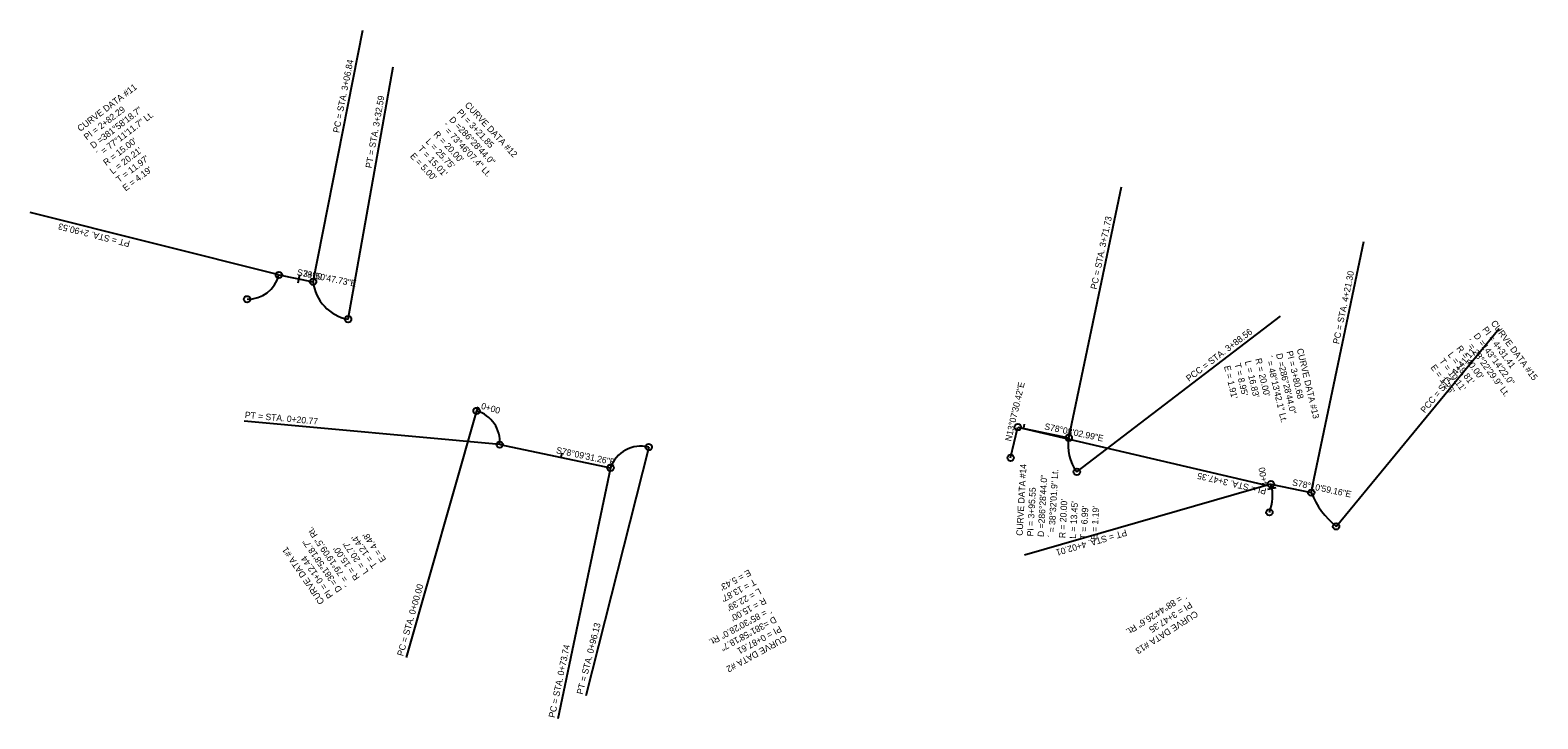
# Model space of a CAD drawing. Extents: x 1158784 to 1165006, y 610007 to 611539.
# Drawn here: x 1164301 to 1165006, y 610067 to 610389 of the extents above; entities that cross this region are included whole.
import ezdxf

# ---------------------------------------------------------------- set-up
doc = ezdxf.new("R2010")
doc.units = 0
for name, color, linetype in [('D_Roadway_Centerline', 7, 'Continuous'), ('D_Roadway_Centerline_Bearings', 7, 'Continuous'), ('D_Roadway_Centerline_CurveData', 7, 'Continuous'), ('D_Roadway_Centerline_Flags', 7, 'Continuous'), ('D_Roadway_Centerline_Text', 7, 'Continuous')]:
    doc.layers.add(name, color=color, linetype=linetype)

msp = doc.modelspace()

# ---------------------------------------------------------------- linework, layer by layer
at = {"layer": 'D_Roadway_Centerline'}
for p, q in [((1164417.28, 610274.76), (1164433.28, 610271.61)), ((1164759.67, 610189.2), (1164763.02, 610203.58)), ((1164763.02, 610203.58), (1164786.87, 610198.57)), ((1164520.59, 610195.37), (1164572.44, 610184.5)), ((1164881.46, 610176.87), (1164900.33, 610172.92))]:
    msp.add_line(p, q, dxfattribs=at)
for centre, radius, start, end in [((1164402.73, 610278.42), 15, 268.70224, 345.88884), ((1164453.17, 610273.75), 20, 186.14707, 259.9158), ((1164505.66, 610196.75), 15, 354.7361, 74.05542), ((1164586.65, 610179.69), 15, 75.80215, 161.30991), ((1164806.52, 610194.82), 20, 169.18321, 217.41157), ((1164862.24, 610171.32), 20, 337.56551, 16.09937), ((1164937.38, 610188), 40, 202.15271, 230.5277)]:
    msp.add_arc(centre, radius, start, end, dxfattribs=at)
at = {"layer": 'D_Roadway_Centerline_Flags'}
for points in [[(1164433.28, 610271.61), (1164456.5, 610389.34)], [(1164449.67, 610254.06), (1164470.68, 610372.2)], [(1164786.87, 610198.57), (1164811.55, 610316)], [(1164417.28, 610274.76), (1164300.9, 610304.02)], [(1164900.33, 610172.92), (1164924.91, 610290.38)], [(1164790.63, 610182.66), (1164885.95, 610255.57)], [(1164911.95, 610157.12), (1164988.24, 610249.76)], [(1164509.78, 610211.17), (1164476.81, 610095.79)], [(1164520.59, 610195.37), (1164401.1, 610206.38)], [(1164763.02, 610203.58), (1164879.88, 610176.33)], [(1164590.33, 610194.24), (1164560.89, 610077.9)], [(1164572.44, 610184.5), (1164547.81, 610067.05)], [(1164881.46, 610176.87), (1164766.16, 610143.59)]]:
    msp.add_lwpolyline(points, dxfattribs=at)
for centre in [(1164417.28, 610274.76), (1164433.28, 610271.61), (1164402.39, 610263.42), (1164449.67, 610254.06), (1164509.78, 610211.17), (1164763.02, 610203.58), (1164520.59, 610195.37), (1164590.33, 610194.24), (1164786.87, 610198.57), (1164759.67, 610189.2), (1164572.44, 610184.5), (1164790.63, 610182.66), (1164881.46, 610176.87), (1164900.33, 610172.92), (1164880.73, 610163.69), (1164911.95, 610157.12)]:
    msp.add_circle(centre, 1.5, dxfattribs=at)
at = {"layer": 'D_Roadway_Centerline_Text'}
for points in [[(1164426.96, 610274.89), (1164426.18, 610270.97)], [(1164510.33, 610213.09), (1164509.23, 610209.25)], [(1164766.02, 610204.99), (1164765.61, 610203.04)], [(1164549.61, 610191.33), (1164549.2, 610189.37)], [(1164879.95, 610174.55), (1164883.88, 610175.27)]]:
    msp.add_lwpolyline(points, dxfattribs=at)

# ---------------------------------------------------------------- texts
at = {"layer": 'D_Roadway_Centerline_Bearings'}
for s, rotation, p in [('S78%%d50\'47.73"E', 348.84659, (1164425.57, 610274.66)), ('N13%%d07\'30.42"E', 76.87488, (1164759.88, 610196.73)), ('S78%%d08\'02.99"E', 348.13416, (1164775.25, 610202.54)), ('S78%%d09\'31.26"E', 348.15868, (1164546.82, 610191.4)), ('S78%%d10\'59.16"E', 348.1831, (1164891.2, 610176.36))]:
    msp.add_text(s, height=3, rotation=rotation, dxfattribs=at).set_placement(p)
at = {"layer": 'D_Roadway_Centerline_CurveData'}
for s, rotation, p in [('CURVE DATA #11', 37.29554, (1164324.37, 610341.69)), ('PI = 2+82.29', 37.29554, (1164327.4, 610337.71)), ('D =381%%d58\'18.7"', 37.29554, (1164330.43, 610333.73)), ('´ = 77%%d11\'11.7" Lt.', 37.29554, (1164333.46, 610329.75)), ('D =286%%d28\'44.0"', 313.03144, (1164496.73, 610347.25)), ('PI = 3+21.85', 313.03144, (1164500.38, 610350.66)), ('CURVE DATA #12', 313.03144, (1164504.04, 610354.07)), ("R = 20.00'", 313.03144, (1164489.42, 610340.42)), ('´ = 73%%d46\'07.4" Lt.', 313.03144, (1164493.07, 610343.83)), ("R = 15.00'", 37.29554, (1164336.49, 610325.78)), ("T = 15.01'", 313.03144, (1164482.11, 610333.6)), ("L = 25.75'", 313.03144, (1164485.76, 610337.01)), ("L = 20.21'", 37.29554, (1164339.52, 610321.8)), ("T = 11.97'", 37.29554, (1164342.55, 610317.82)), ("E = 5.00'", 313.03144, (1164478.45, 610330.19)), ("E = 4.19'", 37.29554, (1164345.58, 610313.84)), ('PI = 4+31.41', 306.34021, (1164980.14, 610249.25)), ('CURVE DATA #15', 306.34021, (1164984.17, 610252.22)), ('´ = 28%%d22\'29.9" Lt.', 306.34021, (1164972.09, 610243.33)), ('D =143%%d14\'22.0"', 306.34021, (1164976.11, 610246.29)), ('´ = 48%%d13\'42.1" Lt.', 283.29739, (1164878.94, 610236.59)), ('D =286%%d28\'44.0"', 283.29739, (1164883.8, 610237.74)), ('PI = 3+80.68', 283.29739, (1164888.67, 610238.89)), ('CURVE DATA #13', 283.29739, (1164893.53, 610240.04)), ("T = 10.11'", 306.34021, (1164960, 610234.44)), ("L = 19.81'", 306.34021, (1164964.03, 610237.4)), ("R = 40.00'", 306.34021, (1164968.06, 610240.37)), ("E = 1.91'", 283.29739, (1164859.47, 610231.99)), ("T = 8.95'", 283.29739, (1164864.34, 610233.14)), ("L = 16.83'", 283.29739, (1164869.2, 610234.29)), ("R = 20.00'", 283.29739, (1164874.07, 610235.44)), ("E = 1.26'", 306.34021, (1164955.98, 610231.48)), ('CURVE DATA #14', 86.83244, (1164765.25, 610152.65)), ('D =286%%d28\'44.0"', 86.83244, (1164775.23, 610152.1)), ('´ = 38%%d32\'01.9" Lt.', 86.83244, (1164780.22, 610151.82)), ('PI = 3+95.55', 86.83244, (1164770.24, 610152.38)), ("R = 20.00'", 86.83244, (1164785.22, 610151.55)), ("L = 13.45'", 86.83244, (1164790.21, 610151.27)), ("T = 6.99'", 86.83244, (1164795.2, 610151)), ("E = 1.19'", 86.83244, (1164800.19, 610150.72)), ('´ = 79%%d19\'09.5" Rt.', 124.39576, (1164451.12, 610130.33)), ("T = 12.44'", 124.39576, (1164463.5, 610138.8)), ("E = 4.48'", 124.39576, (1164467.63, 610141.63)), ('CURVE DATA #1', 124.39576, (1164438.75, 610121.86)), ('D =381%%d58\'18.7"', 124.39576, (1164447, 610127.5)), ("R = 15.00'", 124.39576, (1164455.25, 610133.15)), ("L = 20.77'", 124.39576, (1164459.38, 610135.98)), ('PI = 0+12.44', 124.39576, (1164442.87, 610124.68)), ("E = 5.43'", 208.55603, (1164637.16, 610137.08)), ("T = 13.87'", 208.55603, (1164639.55, 610132.69)), ("L = 22.39'", 208.55603, (1164641.94, 610128.3)), ("R = 15.00'", 208.55603, (1164644.33, 610123.91)), ('´ = 88%%d44\'26.6" Rt.', 212.50452, (1164840.76, 610126.24)), ('´ = 85%%d30\'28.0" Rt.', 208.55603, (1164646.72, 610119.52)), ('CURVE DATA #13', 212.50452, (1164846.13, 610117.81)), ('PI = 3+47.35', 212.50452, (1164843.44, 610122.02)), ('D =381%%d58\'18.7"', 208.55603, (1164649.11, 610115.13)), ('PI = 0+87.61', 208.55603, (1164651.5, 610110.73)), ('CURVE DATA #2', 208.55603, (1164653.89, 610106.34))]:
    msp.add_text(s, height=3, rotation=rotation, dxfattribs=at).set_placement(p)
at = {"layer": 'D_Roadway_Centerline_Flags'}
for s, rotation, p in [('PC = STA. 3+06.84', 78.84659, (1164445.46, 610341.1)), ('PT = STA. 3+32.59', 79.9158, (1164460.68, 610324.58)), ('PC = STA. 3+71.73', 78.13416, (1164799.89, 610267.84)), ('PT = STA. 2+90.53', 165.88884, (1164347.83, 610290.68)), ('PC = STA. 4+21.30', 78.1831, (1164913.31, 610242.27)), ('PCC = STA. 3+88.56', 37.41157, (1164843.13, 610224.71)), ('PCC = STA. 4+41.11', 50.5277, (1164953.46, 610209.89)), ('PT = STA. 0+20.77', 354.7361, (1164401.24, 610207.87)), ('PI = STA. 3+47.35', 166.87488, (1164879.54, 610174.87)), ('PT = STA. 4+02.01', 196.09937, (1164813.56, 610155.71)), ('PC = STA. 0+00.00', 74.05542, (1164475.37, 610096.2)), ('PT = STA. 0+96.13', 75.80215, (1164559.44, 610078.27)), ('PC = STA. 0+73.74', 78.15868, (1164546.35, 610067.36))]:
    msp.add_text(s, height=3, rotation=rotation, dxfattribs=at).set_placement(p)
at = {"layer": 'D_Roadway_Centerline_Text'}
for s, rotation, p in [('3+00', 348.84659, (1164428.33, 610274.11)), ('0+00', 344.05542, (1164511.63, 610212.2)), ('4+00', 100.32989, (1164880.17, 610176.11))]:
    msp.add_text(s, height=3, rotation=rotation, dxfattribs=at).set_placement(p)

doc.saveas('drawing.dxf')
